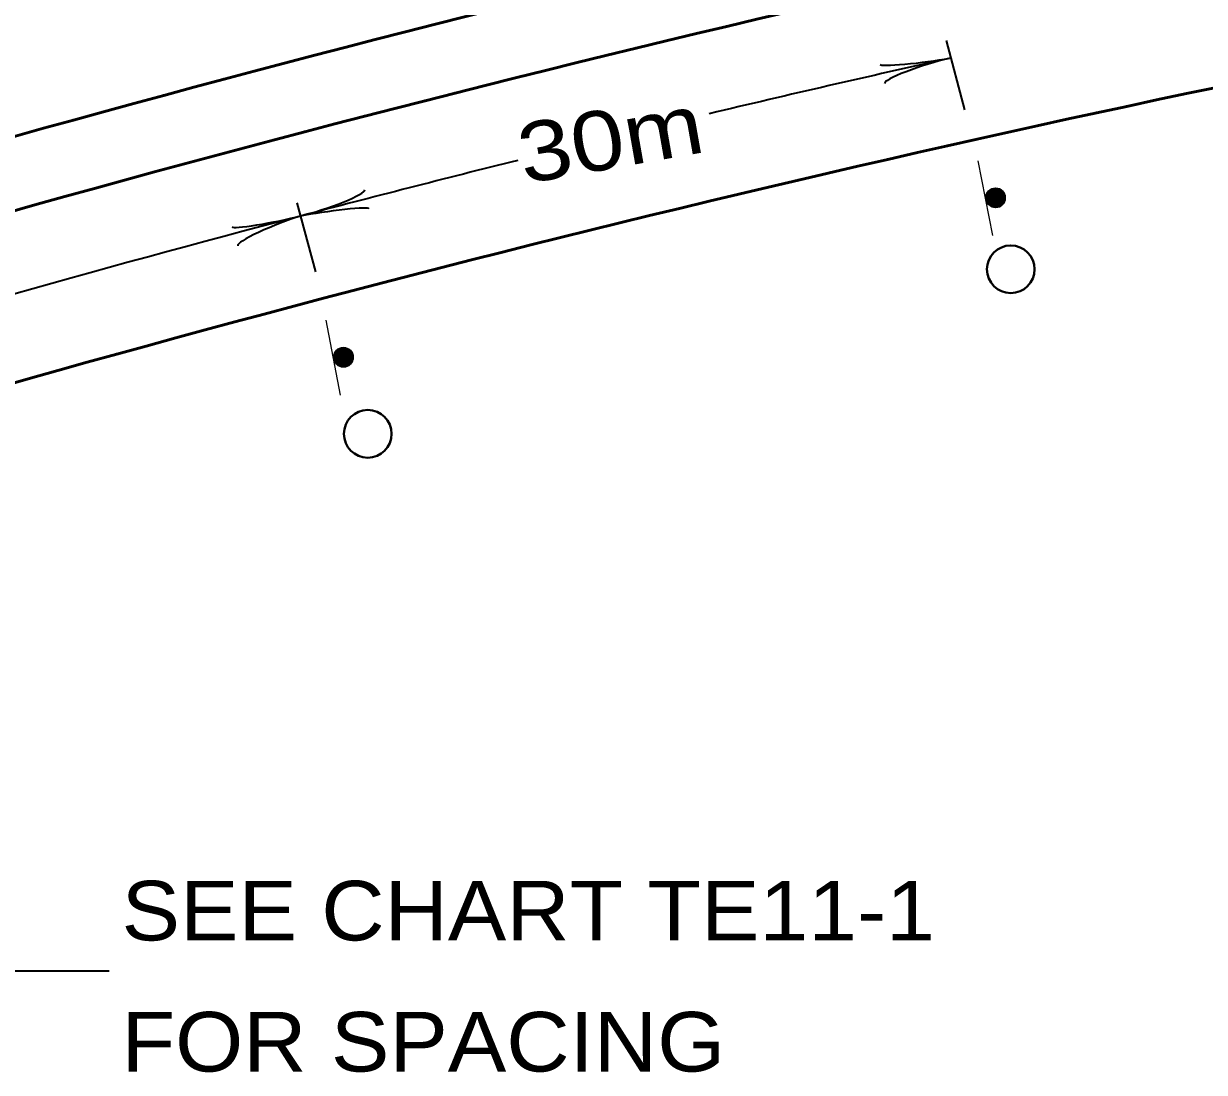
# Model space of a CAD drawing. Extents: x 393 to 1249, y -102 to 530.
# Drawn here: x 567.56 to 615.72, y 270.23 to 312.99 of the extents above; entities that cross this region are included whole.
import ezdxf
from ezdxf.enums import TextEntityAlignment as Align

# ---------------------------------------------------------------- set-up
doc = ezdxf.new("R2010")
doc.units = 0
doc.header["$LTSCALE"] = 0.97
doc.layers.add('1', color=7, linetype='Continuous', lineweight=40)
doc.layers.add('4', color=7, linetype='Continuous', lineweight=25)

msp = doc.modelspace()

# ---------------------------------------------------------------- linework, layer by layer
at = {"layer": '1', "lineweight": 35}
for p, q in [((605.1878, 312.3006), (605.9425, 309.4839)), ((578.7089, 305.6877), (579.4636, 302.8711))]:
    msp.add_line(p, q, dxfattribs=at)
msp.add_lwpolyline([(571.0473, 274.3541), (563.2713, 274.3541), (552.8512, 297.6329)], dxfattribs=at)
at = {"layer": '1'}
for centre, radius in [((607.2046, 305.8877), 0.3791), ((607.1969, 305.8763), 0.35), ((607.2064, 305.8781), 0.3305), ((607.2199, 305.9105), 0.3402), ((607.2046, 305.8877), 0.3013), ((607.2046, 305.8877), 0.2819), ((607.2064, 305.8781), 0.2722), ((607.2064, 305.8781), 0.2527), ((607.2159, 305.88), 0.2335), ((607.2255, 305.8818), 0.2138), ((607.2255, 305.8818), 0.1944), ((607.2101, 305.859), 0.1555), ((607.2446, 305.8856), 0.175), ((607.2083, 305.8686), 0.1069), ((607.2674, 305.8702), 0.1555), ((607.2751, 305.8816), 0.1461), ((607.2864, 305.8739), 0.1166), ((607.296, 305.8757), 0.0977), ((607.2168, 306.0287), 0.00972), ((607.3055, 305.8776), 0.0778), ((607.3246, 305.8813), 0.0583), ((607.3437, 305.885), 0.0389), ((607.3628, 305.8887), 0.0194), ((607.8228, 302.9745), 0.972), ((580.6066, 299.3849), 0.3791), ((580.5989, 299.3735), 0.35), ((580.6084, 299.3754), 0.3305), ((580.6219, 299.4077), 0.3402), ((580.6066, 299.3849), 0.3013), ((580.6066, 299.3849), 0.2819), ((580.6084, 299.3754), 0.2722), ((580.6084, 299.3754), 0.2527), ((580.618, 299.3772), 0.2335), ((580.6275, 299.3791), 0.2138), ((580.6275, 299.3791), 0.1944), ((580.6466, 299.3828), 0.175), ((580.6121, 299.3563), 0.1555), ((580.6103, 299.3658), 0.1069), ((580.6694, 299.3674), 0.1555), ((580.6771, 299.3788), 0.1461), ((580.6885, 299.3711), 0.1166), ((580.698, 299.373), 0.0977), ((580.6188, 299.5259), 0.00972), ((580.7075, 299.3748), 0.0778), ((580.7266, 299.3786), 0.0583), ((580.7457, 299.3823), 0.0389), ((580.7648, 299.386), 0.0194), ((581.5961, 296.2654), 0.972)]:
    msp.add_circle(centre, radius, dxfattribs=at)
at = {"layer": '1', "lineweight": 53}
msp.add_arc((765.1387, -401.6361), 727.4371, 96.79853, 109.38334, dxfattribs=at)
at = {"layer": '1', "lineweight": 35}
for start, end in [(102.58578, 103.37674), (104.0099, 104.73016), (104.73016, 108.80454)]:
    msp.add_arc((763.8173, -398.3831), 727.4371, start, end, dxfattribs=at)
at = {"layer": '1', "lineweight": 53}
for major_axis, ratio, end_param in [((-249.7657, 693.037), 0.999341, 6.2772858), ((-248.777, 690.2937), 0.999339, 6.2770997)]:
    msp.add_ellipse((765.4392, -401.0949), major_axis=major_axis, ratio=ratio, start_param=6.0557933, end_param=end_param, dxfattribs=at)
at = {"layer": '1', "lineweight": 35}
for centre, major_axis, ratio, start_param, end_param in [((604.2003, 311.5356), (1.7031, 0.2086), 0.07063, 3.1407148, 5.41811), ((604.2003, 311.5356), (1.7031, 0.2086), 0.07063, 3.1407148, 5.41811), ((604.3323, 311.0792), (1.6599, 0.5295), 0.122415, 0.8963533, 3.1415927), ((604.3323, 311.0792), (1.6599, 0.5295), 0.122415, 0.8963533, 3.1415927), ((579.8213, 305.6575), (-1.6508, -0.5573), 0.122415, 0.8963533, 3.1415927), ((579.9609, 305.2034), (1.6993, 0.2372), 0.07063, 6.2823074, 8.5597026), ((577.7519, 305.0288), (-1.6839, -0.3291), 0.07063, 6.2823074, 8.5597026), ((577.916, 304.5829), (1.6181, 0.6461), 0.122415, 0.8963533, 3.1415927)]:
    msp.add_ellipse(centre, major_axis=major_axis, ratio=ratio, start_param=start_param, end_param=end_param, dxfattribs=at)
at = {"layer": '4'}
for p, q in [((607.0876, 304.3501), (606.4939, 307.4032)), ((580.4896, 297.8473), (579.896, 300.9006))]:
    msp.add_line(p, q, dxfattribs=at)
for centre in [(607.2027, 305.8972), (580.6047, 299.3945)]:
    msp.add_circle(centre, 0.3985, dxfattribs=at)

# ---------------------------------------------------------------- texts
at = {"layer": '1', "width": 1.2}
msp.add_text('30m', height=2.43, rotation=10, dxfattribs=at).set_placement((591.7031, 307.1096), align=Align.CENTER)
at = {"layer": '1', "width": 1.1}
for s, p in [('SEE CHART TE11-1', (571.5556, 275.6083)), ('FOR SPACING', (571.5556, 270.2623))]:
    msp.add_text(s, height=2.43, dxfattribs=at).set_placement(p)

doc.saveas('drawing.dxf')
